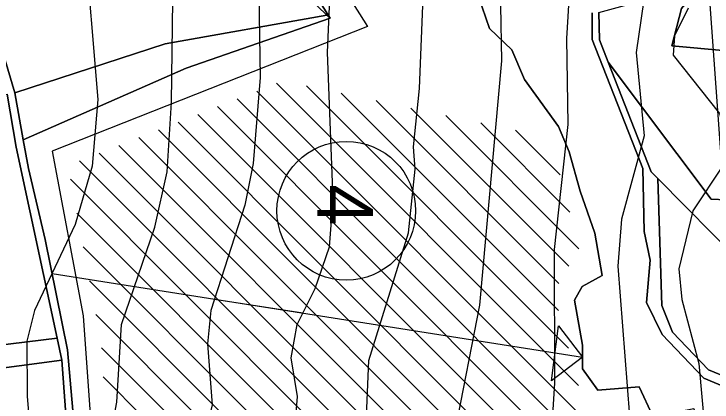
# Model space of a CAD drawing. Extents: x -510989 to -501240, y -1184665 to -1176098.
# Drawn here: x -510144.5 to -509892.7, y -1178671.9 to -1178532.1 of the extents above; entities that cross this region are included whole.
import ezdxf

# ---------------------------------------------------------------- set-up
doc = ezdxf.new("R2010")
doc.units = 0
for name, color, linetype in [('lesni_pozemek', 7, 'Continuous'), ('NAVRH_revitalizace_toku', 7, 'Continuous'), ('orna_puda', 7, 'Continuous'), ('ostatni_plocha_x_neplodna_puda', 7, 'Continuous'), ('ostatni_plocha_x_ostatni_komunikace', 7, 'Continuous'), ('STAV_erozne_ohrozene_plochy', 7, 'Continuous'), ('STAV_odtokove_linie', 7, 'Continuous'), ('STAV_systematicke_odvodneni', 7, 'Continuous'), ('trvaly_travni_porost', 7, 'Continuous'), ('vrstevnice_01', 7, 'Continuous'), ('vrstevnice_02', 7, 'Continuous')]:
    doc.layers.add(name, color=color, linetype=linetype)

msp = doc.modelspace()

# ---------------------------------------------------------------- linework, layer by layer
at = {"layer": 'lesni_pozemek'}
for points in [[(-510091.93, -1178408.03), (-510067.12, -1178475.79), (-510030.4, -1178533.68), (-510031.55, -1178532.57), (-510061.39, -1178503.69), (-510065.75, -1178490.34), (-510082.08, -1178461.41), (-510094.47, -1178425.14), (-510094.15, -1178408.49)], [(-510031.55, -1178532.57), (-510030.4, -1178533.68), (-510082.39, -1178551.61), (-510141.11, -1178577.45), (-510144.13, -1178560.58), (-510089.89, -1178542.86)], [(-510146.91, -1178561.07), (-510143.65, -1178580.09), (-510128.82, -1178648.95), (-510223.37, -1178660.41), (-510242.11, -1178573.72)], [(-510127.13, -1178656.8), (-510221.43, -1178669.35), (-510223.37, -1178660.41), (-510128.82, -1178648.95)], [(-510127.13, -1178656.8), (-510124.74, -1178689.41), (-510122.29, -1178707.36), (-510117.58, -1178726.68), (-510112.7, -1178734.99), (-510110.66, -1178742.05), (-510145.7, -1178746.86), (-510164.15, -1178751.65), (-510235.82, -1178762.37), (-510271, -1178761.12), (-510267.96, -1178754.6), (-510265.59, -1178745.79), (-510207.11, -1178739.59), (-510208.07, -1178731.15), (-510221.43, -1178669.35)]]:
    msp.add_lwpolyline(points, close=True, dxfattribs=at)
msp.add_lwpolyline([(-510061.39, -1178503.69), (-510031.55, -1178532.57), (-510089.89, -1178542.86), (-510144.13, -1178560.58), (-510150.33, -1178540.25), (-510166.93, -1178518.96)], dxfattribs=at)
at = {"layer": 'NAVRH_revitalizace_toku'}
msp.add_lwpolyline([(-510079.08, -1177742.53), (-510057.99, -1177785.41), (-510068.53, -1177883.83), (-510073.46, -1177950.62), (-510054.47, -1178009.67), (-510024.24, -1178091.92), (-509980.66, -1178181.91), (-509942.44, -1178221.73), (-509934.15, -1178235.7), (-509920.62, -1178289.39), (-509918.19, -1178331.5), (-509899.91, -1178389.14), (-509890.77, -1178450.3), (-509893.58, -1178526.93), (-509883.74, -1178663.31)], dxfattribs=at)
at = {"layer": 'orna_puda'}
for points in [[(-510121.93, -1178689.97), (-510125.13, -1178653.17), (-510133.16, -1178613.42), (-510139.25, -1178587.81), (-510141.11, -1178577.45), (-510082.39, -1178551.61), (-510030.4, -1178533.68), (-510067.12, -1178475.79)], [(-509979.56, -1178518.05), (-509972.87, -1178537.36), (-509964.91, -1178545.05), (-509960.25, -1178555.7), (-509948.04, -1178572.63), (-509944.17, -1178581.76), (-509940.24, -1178595.93), (-509934.96, -1178611.11), (-509932.32, -1178626.37), (-509939.53, -1178630.33), (-509942.28, -1178635.26), (-509939.4, -1178651.5), (-509939.35, -1178659.93), (-509933.82, -1178667.66), (-509918.93, -1178666.43), (-509914, -1178676.98)]]:
    msp.add_lwpolyline(points, dxfattribs=at)
msp.add_lwpolyline([(-509898.45, -1178523.77), (-509903.72, -1178530.21), (-509907.1, -1178543.67), (-509887.47, -1178545.47), (-509884.25, -1178596.44), (-509887.51, -1178599.15), (-509892.95, -1178598.8), (-509930.09, -1178549.48), (-509933.25, -1178541.43), (-509933.54, -1178531.63), (-509910.21, -1178525.15)], close=True, dxfattribs=at)
at = {"layer": 'ostatni_plocha_x_neplodna_puda'}
for points in [[(-509886.71, -1178697.22), (-509899.19, -1178674.41), (-509909.05, -1178676.36), (-509911.22, -1178703.41), (-509915.08, -1178704.38), (-509912.94, -1178687.03), (-509914, -1178676.98), (-509918.93, -1178666.43), (-509933.82, -1178667.66), (-509939.35, -1178659.93), (-509939.4, -1178651.5), (-509942.28, -1178635.26), (-509939.53, -1178630.33), (-509932.32, -1178626.37), (-509934.96, -1178611.11), (-509940.24, -1178595.93), (-509944.17, -1178581.76), (-509948.04, -1178572.63), (-509960.25, -1178555.7), (-509964.91, -1178545.05), (-509972.87, -1178537.36), (-509979.56, -1178518.05)], [(-509935.86, -1178531.7), (-509935.86, -1178541.31), (-509917.63, -1178587.83), (-509917.14, -1178610.5), (-509915.02, -1178620.87), (-509916.32, -1178636.1), (-509910.68, -1178647.6), (-509895.56, -1178663.36), (-509878.39, -1178670.57)]]:
    msp.add_lwpolyline(points, dxfattribs=at)
for points in [[(-509892.72, -1178523.77), (-509888.85, -1178523.77), (-509887.47, -1178545.47), (-509907.1, -1178543.67), (-509903.72, -1178530.21), (-509898.45, -1178523.77)], [(-509912.23, -1178591.4), (-509882.54, -1178621.37), (-509880.83, -1178645.35), (-509878.78, -1178666.56), (-509893.96, -1178660.28), (-509906.93, -1178646.77), (-509910.72, -1178637.13)]]:
    msp.add_lwpolyline(points, close=True, dxfattribs=at)
at = {"layer": 'ostatni_plocha_x_ostatni_komunikace'}
for points in [[(-509933.54, -1178531.63), (-509933.25, -1178541.43), (-509930.09, -1178549.48), (-509914.58, -1178589.02), (-509912.23, -1178591.4), (-509910.72, -1178637.13), (-509906.93, -1178646.77), (-509893.96, -1178660.28), (-509878.78, -1178666.56), (-509878.39, -1178670.57), (-509895.56, -1178663.36), (-509910.68, -1178647.6), (-509916.32, -1178636.1), (-509915.02, -1178620.87), (-509917.14, -1178610.5), (-509917.63, -1178587.83), (-509935.86, -1178541.31), (-509935.86, -1178531.7)], [(-510150.33, -1178540.25), (-510144.13, -1178560.58), (-510141.11, -1178577.45), (-510139.25, -1178587.81), (-510133.16, -1178613.42), (-510125.13, -1178653.17), (-510121.93, -1178689.97)], [(-509946.63, -1178931.13), (-509969.07, -1178906.88), (-509971.1, -1178904.69), (-509977.78, -1178899.32), (-509980.32, -1178894.53), (-510036.62, -1178855.12), (-510056.46, -1178841.23), (-510068.99, -1178826.83), (-510070.91, -1178823.71), (-510081.49, -1178802.85), (-510096.15, -1178780.37), (-510105.07, -1178761.42), (-510110.66, -1178742.05), (-510112.7, -1178734.99), (-510117.58, -1178726.68), (-510122.29, -1178707.36), (-510124.74, -1178689.41), (-510127.13, -1178656.8), (-510128.82, -1178648.95), (-510143.65, -1178580.09), (-510146.91, -1178561.07)]]:
    msp.add_lwpolyline(points, dxfattribs=at)
at = {"layer": 'STAV_erozne_ohrozene_plochy'}
for p, q in [((-510049.74, -1178557.12), (-509940.86, -1178666)), ((-510038.96, -1178558), (-509944.45, -1178652.51)), ((-510056.85, -1178559.91), (-509921.54, -1178695.22)), ((-510026.39, -1178560.67), (-509948.04, -1178639.02)), ((-510063.95, -1178562.71), (-509918.81, -1178707.85)), ((-510013.82, -1178563.34), (-509947.89, -1178629.27)), ((-510071.06, -1178565.5), (-509916.08, -1178720.48)), ((-510001.25, -1178566.01), (-509944.27, -1178622.99)), ((-510078.16, -1178568.3), (-509913.35, -1178733.11)), ((-509988.68, -1178568.68), (-509940.66, -1178616.7)), ((-510085.26, -1178571.1), (-509910.61, -1178745.74)), ((-509976.11, -1178571.35), (-509943.92, -1178603.55)), ((-510092.37, -1178573.89), (-509907.88, -1178758.38)), ((-509963.54, -1178574.02), (-509947.44, -1178590.12)), ((-510099.47, -1178576.69), (-509906.83, -1178769.32)), ((-510106.57, -1178579.48), (-509915.42, -1178770.64)), ((-510113.68, -1178582.28), (-509924, -1178771.96)), ((-510120.78, -1178585.08), (-509932.58, -1178773.28)), ((-510124.07, -1178591.69), (-509941.16, -1178774.6)), ((-510121.78, -1178603.87), (-509949.74, -1178775.91)), ((-510119.5, -1178616.06), (-509958.32, -1178777.23)), ((-510117.21, -1178628.24), (-509966.9, -1178778.55)), ((-510114.93, -1178640.43), (-509975.48, -1178779.87)), ((-510112.87, -1178652.38), (-509984.07, -1178781.19)), ((-510112.31, -1178662.84), (-509992.65, -1178782.5))]:
    msp.add_line(p, q, dxfattribs=at)
at = {"layer": 'STAV_odtokove_linie'}
for p, q in [((-510130.7, -1178625.61), (-509939.38, -1178655.72)), ((-510072.15, -1178634.82), (-510040.23, -1178639.85))]:
    msp.add_line(p, q, dxfattribs=at)
msp.add_lwpolyline([(-509947.98, -1178644.49), (-509939.38, -1178655.72), (-509950.6, -1178664.32)], close=True, dxfattribs=at)
msp.add_circle((-510024.59, -1178603.04), 25, dxfattribs=at)
at = {"layer": 'STAV_systematicke_odvodneni'}
for p, q in [((-510057.5, -1178472.97), (-510016.88, -1178536.61)), ((-510016.88, -1178536.61), (-510130.73, -1178581.53)), ((-510130.73, -1178581.53), (-510119.51, -1178640.88)), ((-510119.51, -1178640.88), (-510116.3, -1178685.8))]:
    msp.add_line(p, q, dxfattribs=at)
at = {"layer": 'trvaly_travni_porost'}
msp.add_lwpolyline([(-509930.09, -1178549.48), (-509892.95, -1178598.8), (-509887.51, -1178599.15), (-509884.25, -1178596.44), (-509883.8, -1178603.54), (-509883.67, -1178605.55), (-509882.54, -1178621.37), (-509912.23, -1178591.4), (-509914.58, -1178589.02)], close=True, dxfattribs=at)
at = {"layer": 'vrstevnice_01'}
for points in [[(-509977.91, -1178946), (-510000.5, -1178895), (-510036.81, -1178856), (-510036.81, -1178849), (-510034.19, -1178842), (-510033.59, -1178834), (-510038.69, -1178819), (-510038, -1178793), (-510032, -1178750), (-510035.69, -1178727), (-510042, -1178718), (-510053.19, -1178708), (-510056.41, -1178701), (-510055.31, -1178697), (-510045.69, -1178688), (-510043.31, -1178683), (-510042.19, -1178670), (-510044.5, -1178656), (-510042.31, -1178644), (-510035.81, -1178631), (-510030.69, -1178616), (-510029.31, -1178599), (-510031.41, -1178546), (-510029.19, -1178496)], [(-509913.81, -1178503), (-509920, -1178546), (-509917.19, -1178576), (-509925.31, -1178606), (-509926.69, -1178623), (-509922.41, -1178677), (-509927.31, -1178745), (-509926.41, -1178778), (-509918.31, -1178805), (-509907.69, -1178824), (-509877.91, -1178861), (-509867.31, -1178877), (-509859.5, -1178892), (-509851.81, -1178924)], [(-509969.31, -1178509), (-509968.59, -1178549), (-509976.59, -1178637), (-509985.31, -1178682), (-509986.5, -1178703), (-509982.69, -1178725), (-509980.5, -1178746), (-509980.91, -1178764), (-509985.19, -1178784), (-510000.81, -1178811), (-509999.81, -1178823), (-509996.31, -1178830), (-509982.09, -1178840), (-509959.59, -1178851), (-509949.69, -1178858), (-509941.5, -1178869), (-509938.59, -1178876), (-509920.19, -1178906), (-509915.19, -1178911), (-509909.19, -1178930)], [(-510056.5, -1178934), (-510090.31, -1178859), (-510096.19, -1178840), (-510101, -1178812), (-510100.09, -1178770), (-510097.81, -1178742), (-510098.59, -1178733), (-510104.41, -1178711), (-510106.41, -1178708), (-510110.41, -1178688), (-510107.31, -1178672), (-510105.69, -1178644), (-510093.59, -1178609), (-510089.19, -1178589), (-510087.59, -1178564), (-510087.19, -1178527)]]:
    msp.add_lwpolyline(points, dxfattribs=at)
at = {"layer": 'vrstevnice_02'}
for points in [[(-510119.09, -1178504), (-510114.19, -1178563), (-510116.19, -1178587), (-510122.41, -1178608), (-510137, -1178639), (-510139.81, -1178650), (-510139.69, -1178670), (-510135.5, -1178720), (-510134.81, -1178744), (-510138.19, -1178816), (-510134.59, -1178839), (-510125.41, -1178867), (-510095.81, -1178933), (-510084.19, -1178971), (-510081.31, -1178989), (-510082.81, -1179004), (-510089.31, -1179031), (-510089.91, -1179038), (-510087.81, -1179050), (-510080.69, -1179074), (-510080.41, -1179096), (-510084.69, -1179115), (-510105, -1179170)], [(-510056.31, -1178510), (-510055.69, -1178555), (-510058.19, -1178586), (-510061.19, -1178601), (-510073.5, -1178639), (-510074.69, -1178651), (-510072.91, -1178673), (-510074.41, -1178679), (-510081.09, -1178692), (-510081.91, -1178702), (-510080.19, -1178709), (-510067.91, -1178737), (-510065.59, -1178749), (-510070.91, -1178807), (-510055.81, -1178849), (-510050.59, -1178867), (-510032.09, -1178914), (-510008, -1178964)], [(-509942.5, -1178993), (-509960.69, -1178914), (-509971.59, -1178890), (-509987, -1178864), (-510016.09, -1178841), (-510021.31, -1178834), (-510020.19, -1178816), (-510011, -1178789), (-510007.81, -1178765), (-510008.59, -1178746), (-510013.31, -1178730), (-510022.31, -1178713), (-510025.59, -1178703), (-510025, -1178696), (-510017.31, -1178677), (-510016.41, -1178657), (-510002.09, -1178611), (-509999.69, -1178588), (-510000.31, -1178580), (-509998.19, -1178559), (-509996.69, -1178523)], [(-509885.09, -1178936), (-509889.09, -1178914), (-509899.31, -1178878), (-509906.91, -1178861), (-509916.69, -1178848), (-509931.81, -1178837), (-509944.41, -1178829), (-509950.41, -1178822), (-509955, -1178809), (-509955.91, -1178789), (-509952, -1178754), (-509950.81, -1178727), (-509951.31, -1178696), (-509949.41, -1178665), (-509949.5, -1178617), (-509944.5, -1178572), (-509945.09, -1178541), (-509944, -1178523)], [(-509901.31, -1178530), (-509906.19, -1178540), (-509906.69, -1178547), (-509890, -1178568), (-509886.91, -1178578), (-509888.91, -1178587), (-509899.59, -1178603), (-509904.69, -1178624), (-509903.59, -1178635), (-509897.41, -1178658), (-509894.91, -1178686), (-509900.69, -1178717), (-509902.5, -1178719), (-509898.81, -1178758), (-509886.69, -1178801), (-509876.59, -1178824), (-509859.59, -1178849), (-509843.41, -1178863), (-509819.91, -1178879), (-509808.91, -1178889), (-509801.69, -1178902), (-509798.59, -1178913), (-509792.5, -1178922)]]:
    msp.add_lwpolyline(points, dxfattribs=at)

# ---------------------------------------------------------------- texts
at = {"layer": 'STAV_odtokove_linie'}
msp.add_text('4', height=20, rotation=270, dxfattribs=at).set_placement((-510034.99, -1178593.45))

doc.saveas('drawing.dxf')
